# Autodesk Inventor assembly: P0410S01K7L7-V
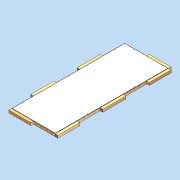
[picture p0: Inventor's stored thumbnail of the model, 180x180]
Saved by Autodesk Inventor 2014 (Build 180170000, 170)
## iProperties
Created: 2011-04
Part Number: P0410S01K7L7-V
Document SubType Name: Assembly
Designer: david.appleford
Description: 1w x 2.5w 01 Panel - 7 Locks 7 Lugs
Mass: 59000 g
Surface Area: 87197.2 cm^2
Volume: 292896 cm^3
Density: 0.201437 g/cm^3
Cost Center: £193.00
Justset: False
Title: 1w x 2.5w 01 Panel - 7 Locks 7 Lugs
Author: david.appleford
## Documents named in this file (4)
- C:\Documents and Settings\john.everitt\Local Settings\My Documents\Vault\Production MkII\VIRTUAL ELEMENTS\Virtual Walls\Virtual Timber + MgO\P0410S01K7L7-V.iam
- C:\Documents and Settings\john.everitt\Local Settings\My Documents\Vault\Production MkII\Virtual Elements\Virtual Walls\Virtual Timber + MgO\P0410S01K7-V.ipt
- C:\Documents and Settings\john.everitt\Local Settings\My Documents\Vault\Production MkII\VIRTUAL ELEMENTS\Virtual Lugs\LA02C3CC-V.ipt
- C:\Documents and Settings\john.everitt\Local Settings\My Documents\Vault\Production MkII\VIRTUAL ELEMENTS\Virtual Lugs\LA02M3CC-V.ipt
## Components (8 placed, 3 different names)
1. P0410S01K7-V:1 — Mate:1, Flush:1, Flush:2, Mate:2, Flush:3, Flush:4, Mate:4, Flush:7, Flush:8, Mate:5, Mate:6, Flush:9, Flush:10, Mate:7, Mate:8, Flush:11, Flush:12
2. LA02C3CC-V:1 — Mate:1, Flush:1, Flush:2, Mate:9, Mate:13
3. LA02C3CC-V:2 — Mate:2, Flush:3, Flush:4
4. LA02C3CC-V:3 — Mate:4, Flush:7, Flush:8
5. LA02M3CC-V:1 — Mate:6, Flush:9, Mate:12
6. LA02M3CC-V:2 — Mate:5, Flush:10, Mate:12, Mate:13
7. LA02C3CC-V:4 — Mate:8, Flush:12, Mate:10
8. LA02M3CC-V:3 — Mate:7, Flush:11, Mate:9, Mate:10
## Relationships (21: Mate 11, Flush 10)
- Mate:1: P0410S01K7-V:1 ↔ LA02C3CC-V:1
- Flush:1: P0410S01K7-V:1 ↔ LA02C3CC-V:1
- Flush:2: P0410S01K7-V:1 ↔ LA02C3CC-V:1
- Mate:2: P0410S01K7-V:1 ↔ LA02C3CC-V:2
- Flush:3: P0410S01K7-V:1 ↔ LA02C3CC-V:2
- Flush:4: P0410S01K7-V:1 ↔ LA02C3CC-V:2
- Mate:4: P0410S01K7-V:1 ↔ LA02C3CC-V:3
- Flush:7: P0410S01K7-V:1 ↔ LA02C3CC-V:3
- Flush:8: P0410S01K7-V:1 ↔ LA02C3CC-V:3
- Mate:5: P0410S01K7-V:1 ↔ LA02M3CC-V:2
- Mate:6: P0410S01K7-V:1 ↔ LA02M3CC-V:1
- Flush:9: P0410S01K7-V:1 ↔ LA02M3CC-V:1
- Flush:10: P0410S01K7-V:1 ↔ LA02M3CC-V:2
- Mate:7: P0410S01K7-V:1 ↔ LA02M3CC-V:3
- Mate:8: P0410S01K7-V:1 ↔ LA02C3CC-V:4
- Flush:11: P0410S01K7-V:1 ↔ LA02M3CC-V:3
- Flush:12: P0410S01K7-V:1 ↔ LA02C3CC-V:4
- Mate:9: LA02C3CC-V:1 ↔ LA02M3CC-V:3
- Mate:10: LA02C3CC-V:4 ↔ LA02M3CC-V:3
- Mate:12: LA02M3CC-V:1 ↔ LA02M3CC-V:2
- Mate:13: LA02C3CC-V:1 ↔ LA02M3CC-V:2
## Named parameters: t = 1 mm, Cl = 2 mm
